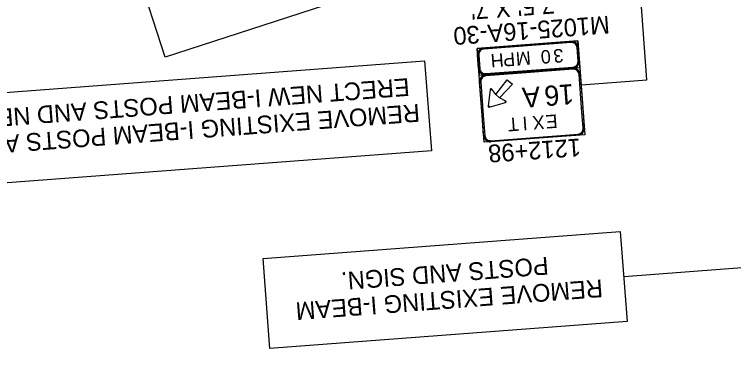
# Model space of a CAD drawing. Extents: x 2001876 to 2025694, y 804561 to 868938.
# Drawn here: x 2021701 to 2022513, y 811858 to 812249 of the extents above; entities that cross this region are included whole.
import ezdxf

# ---------------------------------------------------------------- set-up
doc = ezdxf.new("R2010")
doc.units = 0
for name, color, linetype in [('Level 30', 7, 'Continuous'), ('RD_PD_CLEAR ZONE', 7, 'Continuous'), ('TR SN EXTRUDED PANEL SIGNS - GROUND MOUNTED', 7, 'Continuous'), ('TR SN EXTRUDED PANEL SIGNS- MOUNTED OVERHEAD', 7, 'Continuous')]:
    doc.layers.add(name, color=color, linetype=linetype)

msp = doc.modelspace()

# ---------------------------------------------------------------- linework, layer by layer
at = {"layer": 'RD_PD_CLEAR ZONE'}
msp.add_arc((2020794.27, 812071.86), 2864.79, 355.71297, 56.96135, dxfattribs=at)
at = {"layer": 'TR SN EXTRUDED PANEL SIGNS - GROUND MOUNTED'}
for p, q in [((2022415.1, 812175.07), (2022400.7, 812365.86)), ((2022329.37, 812218.57), (2022329.47, 812217.31)), ((2022230.95, 812209.87), (2022230.85, 812211.14)), ((2022336.26, 812211.47), (2022337.52, 812211.56)), ((2022223.85, 812202.98), (2022225.11, 812203.08)), ((2022338.67, 812196.41), (2022337.4, 812196.31)), ((2022226.25, 812187.92), (2022224.99, 812187.83)), ((2022331.57, 812189.52), (2022331.66, 812188.26)), ((2022331.66, 812188.26), (2022331.76, 812186.99)), ((2022233.14, 812180.82), (2022233.05, 812182.08)), ((2022233.24, 812179.56), (2022233.14, 812180.82)), ((2022338.55, 812181.16), (2022339.81, 812181.25)), ((2022226.13, 812172.67), (2022227.4, 812172.77)), ((2022341.04, 812169.48), (2022415.1, 812175.07)), ((2022238.12, 812164.22), (2022239.06, 812164.1)), ((2022239.06, 812164.1), (2022239.84, 812164.65)), ((2022236.78, 812145.18), (2022235.84, 812145.29)), ((2022237.04, 812144.27), (2022236.78, 812145.18)), ((2022255.58, 812151.12), (2022255.15, 812150.27)), ((2022255.15, 812150.27), (2022255.4, 812149.36)), ((2022344.39, 812120.62), (2022343.12, 812120.53)), ((2022231.97, 812112.14), (2022230.71, 812112.04)), ((2022337.29, 812113.74), (2022337.38, 812112.47)), ((2022238.86, 812105.04), (2022238.77, 812106.3)), ((2022388.87, 811952.72), (2022935.98, 811994.01))]:
    msp.add_line(p, q, dxfattribs=at)
for points in [[(2022336.95, 812219.14), (2022223.27, 812210.56), (2022225.56, 812180.25), (2022339.24, 812188.83), (2022336.95, 812219.14)], [(2022344.96, 812113.04), (2022231.28, 812104.47), (2022223.27, 812210.56), (2022336.95, 812219.14)], [(2022329.47, 812217.31), (2022230.95, 812209.87), (2022230.85, 812211.14), (2022329.37, 812218.57), (2022329.47, 812217.31)], [(2022337.4, 812196.31), (2022336.26, 812211.47), (2022337.52, 812211.56), (2022338.67, 812196.41), (2022337.4, 812196.31)], [(2022225.11, 812203.08), (2022226.25, 812187.92), (2022224.99, 812187.83), (2022223.85, 812202.98), (2022225.11, 812203.08)], [(2022171.75, 812094.96), (2021507.68, 812044.84), (2021500.02, 812146.35), (2022164.09, 812196.47)], [(2022233.05, 812182.08), (2022331.57, 812189.52), (2022331.66, 812188.26), (2022233.14, 812180.82), (2022233.05, 812182.08)], [(2022331.76, 812186.99), (2022263.55, 812181.85), (2022263.45, 812183.11), (2022331.66, 812188.26), (2022331.76, 812186.99)], [(2022263.55, 812181.85), (2022233.24, 812179.56), (2022233.14, 812180.82), (2022263.45, 812183.11), (2022263.55, 812181.85)], [(2022341.41, 812143.26), (2022338.55, 812181.16), (2022339.81, 812181.25), (2022342.67, 812143.36), (2022341.41, 812143.26)], [(2022227.4, 812172.77), (2022230.26, 812134.87), (2022228.99, 812134.78), (2022226.13, 812172.67), (2022227.4, 812172.77)], [(2022257.43, 812175.03), (2022263.2, 812170.08), (2022248.65, 812154.61), (2022244.33, 812158.33), (2022257.43, 812175.03)], [(2022236.78, 812145.18), (2022237.04, 812144.27), (2022255.4, 812149.36), (2022255.15, 812150.27), (2022255.58, 812151.12), (2022248.65, 812154.61), (2022244.33, 812158.33), (2022239.84, 812164.65), (2022239.06, 812164.1), (2022238.12, 812164.22), (2022235.84, 812145.29), (2022236.78, 812145.18)], [(2022343.12, 812120.53), (2022341.41, 812143.26), (2022342.67, 812143.36), (2022344.39, 812120.62), (2022343.12, 812120.53)], [(2022230.26, 812134.87), (2022231.97, 812112.14), (2022230.71, 812112.04), (2022228.99, 812134.78), (2022230.26, 812134.87)], [(2022238.77, 812106.3), (2022337.29, 812113.74), (2022337.38, 812112.47), (2022238.86, 812105.04), (2022238.77, 812106.3)], [(2022392.7, 811901.96), (2021989.18, 811871.51), (2021981.52, 811973.02), (2022385.04, 812003.47)]]:
    msp.add_lwpolyline(points, close=True, dxfattribs=at)
for centre, radius, start, end in [((2022329.95, 812210.99), 7.6, 4.31584, 94.31605), ((2022329.95, 812210.99), 6.33, 4.31584, 94.31605), ((2022231.43, 812203.56), 7.6, 94.31605, 184.31626), ((2022231.43, 812203.56), 6.33, 94.31605, 184.31626), ((2022331.09, 812195.84), 6.33, 274.3162, 4.31584), ((2022331.09, 812195.84), 7.6, 274.3162, 4.31584), ((2022232.57, 812188.4), 7.6, 184.31599, 274.3162), ((2022232.57, 812188.4), 6.33, 184.31599, 274.3162), ((2022332.23, 812180.68), 7.6, 4.31584, 94.31605), ((2022332.23, 812180.68), 6.33, 4.31584, 94.31605), ((2022233.71, 812173.24), 7.6, 94.31605, 184.31626), ((2022233.71, 812173.24), 6.33, 94.31605, 184.31626), ((2022239.06, 812164.1), 0.95, 35.35411, 173.13786), ((2022236.78, 812145.18), 0.95, 173.13786, 285.49373), ((2022255.15, 812150.27), 0.95, 285.49404, 63.27836), ((2022336.81, 812120.05), 6.33, 274.3162, 4.31584), ((2022336.81, 812120.05), 7.6, 274.3162, 4.31584), ((2022238.29, 812112.62), 7.6, 184.31599, 274.3162), ((2022238.29, 812112.62), 6.33, 184.31599, 274.3162)]:
    msp.add_arc(centre, radius, start, end, dxfattribs=at)
at = {"layer": 'TR SN EXTRUDED PANEL SIGNS- MOUNTED OVERHEAD'}
msp.add_lwpolyline([(2022495.73, 812403.61), (2021870.93, 812200.78), (2021838.84, 812299.62), (2022463.65, 812502.46)], close=True, dxfattribs=at)

# ---------------------------------------------------------------- texts
at = {"layer": 'Level 30'}
msp.add_text('M1025-16A-30', height=20, rotation=184.31599, dxfattribs=at).set_placement((2022372.26, 812247.62))
at = {"layer": 'TR SN EXTRUDED PANEL SIGNS - GROUND MOUNTED'}
for s, height, rotation, p in [("7.5' X 7'", 20, 184.31599, (2022310.19, 812270.15)), ('0', 15.2, 184.31599, (2022305.92, 812209.18)), ('3', 15.2, 184.31599, (2022320.26, 812210.26)), ('H', 15.2, 184.31599, (2022252.76, 812205.17)), ('P', 15.2, 184.31599, (2022265.61, 812206.14)), ('M', 15.2, 184.31599, (2022283.4, 812207.48)), ('ERECT NEW I-BEAM POSTS AND NEW SIGN.', 20, 184.31599, (2022146.26, 812177.05)), ('A', 22.8, 184.31599, (2022293.73, 812167.61)), ('6', 22.8, 184.31599, (2022315.35, 812169.24)), ('1', 22.8, 184.31599, (2022331.82, 812170.49)), ('REMOVE EXISTING I-BEAM POSTS AND SIGN.', 20, 184.31599, (2022157.83, 812147.84)), ('E', 15.2, 184.31599, (2022313.57, 812136.08)), ('T', 15.2, 184.31599, (2022269.9, 812132.79)), ('I', 15.2, 184.31599, (2022279.66, 812133.52)), ('X', 15.2, 184.31599, (2022298.93, 812134.98)), ('1212+98', 20, 184.08848, (2022339.8, 812108.86)), ('POSTS AND SIGN.', 20, 184.31599, (2022303.24, 811975.04)), ('REMOVE EXISTING I-BEAM', 20, 184.31599, (2022364.5, 811949.58))]:
    msp.add_text(s, height=height, rotation=rotation, dxfattribs=at).set_placement(p)

doc.saveas('drawing.dxf')
